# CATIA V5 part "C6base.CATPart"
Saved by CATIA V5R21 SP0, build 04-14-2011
Part number: C6base
Bounding box of the stored display mesh (mm): x -6.35 to 0, y -76.2 to 76.2, z 0 to 114.3
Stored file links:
  C:\Users\User\Desktop\B.D.M.A\Chapter6\C6base.CATPart
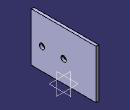
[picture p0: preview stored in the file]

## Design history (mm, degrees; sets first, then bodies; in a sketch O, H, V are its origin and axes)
Body1 (main body)
  Sketch1 on yz-plane, origin (0, 0, 0), H (0, 1, 0), V (0, 0, 1)
    point P1 (-76.2, 0)
    line L1 (-76.2, 0) -> (76.2, 0)
    line L2 (76.2, 0) -> (76.2, 114.3)
    line L3 (76.2, 114.3) -> (-76.2, 114.3)
    line L4 (-76.2, 114.3) -> (-76.2, 0)
    circle A1 centre (0, 50.8) radius 6.35
    point P5 (0, 50.8)
    circle A2 centre (-50.8, 50.8) radius 6.35
    point P6 (-50.8, 50.8)
    length L1 = 152.4
    length L4 = 114.3
    distance P5 H = 50.8
    distance P6 H = 50.8
    distance P6 P5 = 50.8
    radius A1 = 6.35
    radius A2 = 6.35
    coincidence: P1 H, P5 V
    horizontal: L1 H, L3 H
    vertical: L2 V, L4 V
    symmetry: L4 L2 V
  Pad1: profile Sketch1, direction (-1, 0, 0), length 6.35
